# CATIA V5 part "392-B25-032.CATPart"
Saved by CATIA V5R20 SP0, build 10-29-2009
Part number: 392-B25-032
Definition: NONE
Nomenclature: 392-B25-032
Source: Unknown
Description: 392-B25-032
Bounding box of the stored display mesh (mm): x 0 to 32, y -12.335 to 12.335, z -12.25 to 12.064
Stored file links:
  C:\Users\Utente\Desktop\IO LAVORO\3D X SITO CF\X SITO\3D files 392B\392-B25-032.CATPart
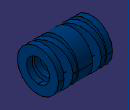
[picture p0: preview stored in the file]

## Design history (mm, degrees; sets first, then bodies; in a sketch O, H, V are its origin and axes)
Body1 "392-B25-032" (main body)
  Solid1: solid without history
